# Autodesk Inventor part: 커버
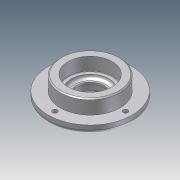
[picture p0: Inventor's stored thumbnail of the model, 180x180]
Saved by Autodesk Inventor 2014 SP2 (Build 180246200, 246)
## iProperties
Company: 한국ATC센터
Created: 2014-10
Part Number: 커버
Document SubType Name: Modeling
Designer: KYOUNG IL JANG
Density: 1 g/cm^3
Mass: 44.7286 g
Surface Area: 161.165 cm^2
Volume: 44.7286 cm^3
Material: 일반
Appearance: 기본값
Author: KYOUNG IL JANG
Revision Number: 1
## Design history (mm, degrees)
sketch "스케치1"
  geometry: C1 r 38 at (0, 0); 1 further point
  constraints: 1 centre point, 1 coincident
  dimensions: "d0" = 76 diameter of C1
extrude "돌출1" new body sketch "스케치1" distance "d1" = 7; taper "d2" = 0 deg
sketch "스케치2"
  geometry: C1 r 27 at (0, 0); 1 further point
  constraints: 1 centre point, 1 coincident
  dimensions: "d3" = 54 diameter of C1
extrude "돌출2" join sketch "스케치2" distance "d4" = 13; taper "d5" = 0 deg
sketch "스케치3"
  geometry: C1 r 20 at (0, 0); 1 further point
  constraints: 1 centre point, 1 coincident
  dimensions: "d6" = 40 diameter of C1
extrude "돌출3" join sketch "스케치3" distance "d7" = 5; taper "d8" = 0 deg
hole "구멍1" diameter "d11" = 25; stored, may be unused: countersink angle "d15" = 90 deg, drill point angle "d17" = 118 deg; dims "d9" = 10, "d10" = 10, "d12" = 6, "d13" = 32, "d14" = 8.3, "d16" = 8
hole "구멍2" diameter "d20" = 34; stored, may be unused: countersink angle "d24" = 90 deg, drill point angle "d26" = 0 deg; dims "d18" = 10, "d19" = 10, "d21" = 6, "d22" = 40, "d23" = 12, "d25" = 3
fillet "모깎기2" dims "d34" = 3
fillet "모깎기1" dims "d27" = 0.3
chamfer "모따기1" distance "d28" = 1; stored, may be unused: second distance "d29" = 2, angle "d30" = 45 deg
chamfer "모따기2" distance "d31" = 1.2; stored, may be unused: second distance "d32" = 2, angle "d33" = 30 deg
sketch "스케치4" dims "d35" = 64
  geometry: 3 further points
  constraints: 2 horizontal alignment, 1 coincident, 2 other
hole "구멍3" sketch "스케치4" at (32, 0) diameter "d36" = 4.5; stored, may be unused: countersink angle "d40" = 90 deg, drill point angle "d42" = 118 deg; dims "d37" = 6, "d38" = 8, "d39" = 4.4, "d41" = 13
node "솔리드1"
pattern_circular "원형 패턴1" dims angle "d44" = 360 deg
